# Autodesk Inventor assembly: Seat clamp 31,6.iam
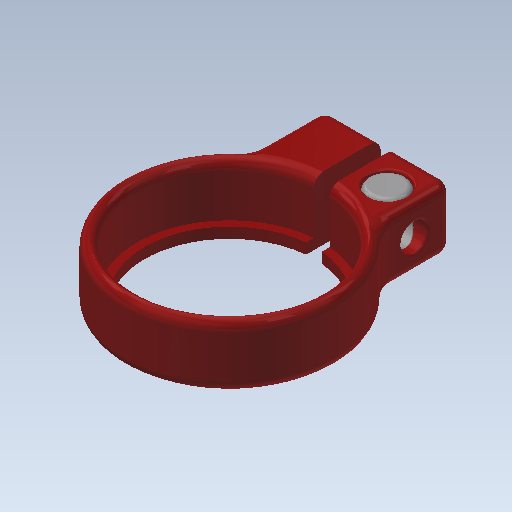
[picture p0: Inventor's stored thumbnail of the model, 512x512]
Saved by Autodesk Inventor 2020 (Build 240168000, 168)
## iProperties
Created: 2017-10
Part Number: Seat clamp 31,6.iam
Material: Ogólny
Document SubType Name: Assembly
Designer: Tomasz
Sending System: SolidWorks 2017
Last Author: Tomasz
Last Saved: 2017-10-01
Author: Tomasz
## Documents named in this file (5)
- C:\Users\bruno\Documents\1-Cours-2020-21\1STI2D-2020-21\IT\6. Antivol\Inventor-Antivol\INVENTOR 2018_Steel Hardtail B+\Seat clamp 31,6.iam.iam
- C:\Users\bruno\Documents\1-Cours-2020-21\1STI2D-2020-21\IT\6. Antivol\Inventor-Antivol\INVENTOR 2018_Steel Hardtail B+\lock nut.ipt.ipt
- C:\Users\bruno\Documents\1-Cours-2020-21\1STI2D-2020-21\IT\6. Antivol\Inventor-Antivol\INVENTOR 2018_Steel Hardtail B+\Lock ring.ipt.ipt
- lock nut.ipt
- Lock ring.ipt
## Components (2 placed, 2 different names)
1. lock nut.ipt:1
2. Lock ring.ipt:1
